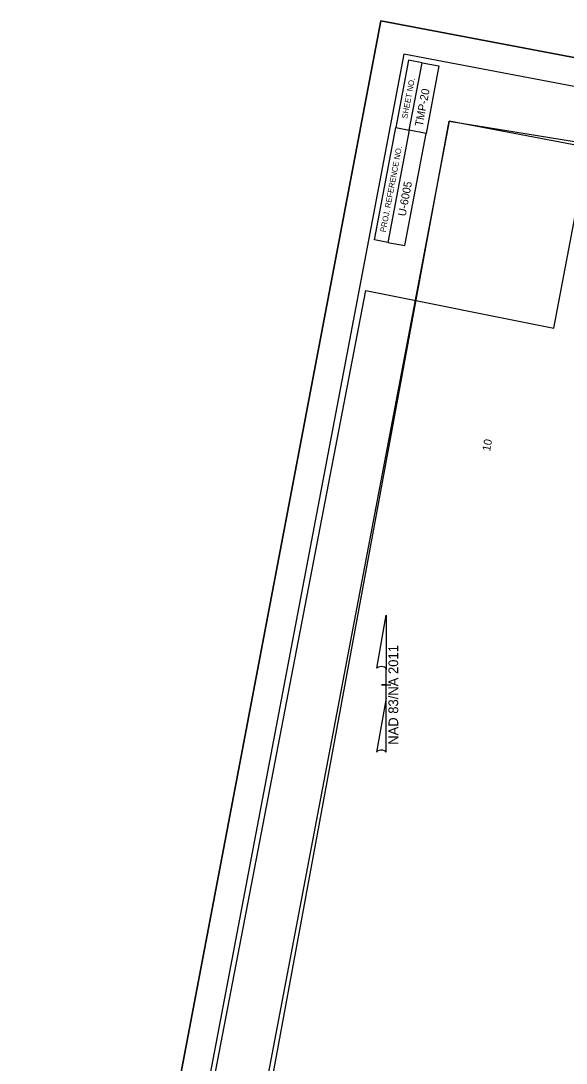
# Model space of a CAD drawing. Extents: x 1615680 to 1617075, y 898420 to 901168.
# Drawn here: x 1615680 to 1616157, y 900256 to 901168 of the extents above; entities that cross this region are included whole.
import ezdxf

# ---------------------------------------------------------------- set-up
doc = ezdxf.new("R2010")
doc.units = 0
for name, color, linetype in [('DEV BORDER CELL', 7, 'Continuous'), ('Prop Horizontal Alignment Tick Label', 7, 'Continuous'), ('Prop North Arrow NAD83 for Plan Sheets CELL', 7, 'Continuous'), ('Scratch_Level_0', 7, 'Continuous'), ('Sheet Clip Boundary CELL', 7, 'Continuous'), ('Sheet Plot Border Outside CELL', 7, 'Continuous')]:
    doc.layers.add(name, color=color, linetype=linetype)

msp = doc.modelspace()

# ---------------------------------------------------------------- linework, layer by layer
at = {"layer": 'DEV BORDER CELL'}
msp.add_line((1616019.39, 901072.79), (1616030.58, 901131.73), dxfattribs=at)
for points in [[(1616014.55, 901139.21), (1615734.74, 899665.53), (1616766.32, 899469.67), (1617046.12, 900943.35)], [(1616019.39, 901072.79), (1616030.58, 901131.73), (1616018.79, 901133.97), (1616007.6, 901075.03)], [(1616019.39, 901072.79), (1616030.58, 901131.73), (1616045.31, 901128.94), (1616034.12, 901069.99)], [(1615988.94, 900976.78), (1616007.6, 901075.03), (1616019.39, 901072.79), (1616000.73, 900974.54)], [(1616019.39, 901072.79), (1616000.73, 900974.54), (1616015.47, 900971.74), (1616034.12, 901069.99)]]:
    msp.add_lwpolyline(points, close=True, dxfattribs=at)
at = {"layer": 'Prop North Arrow NAD83 for Plan Sheets CELL'}
for p, q in [((1615990.96, 900601.99), (1615999.16, 900648.34)), ((1615999.21, 900648.34), (1615999.16, 900648.34)), ((1615999.21, 900648.34), (1615999.16, 900648.34)), ((1615999.21, 900648.34), (1615999.21, 900600.54)), ((1615999.21, 900575.74), (1615999.21, 900601.94)), ((1615999.21, 900600.54), (1615999.21, 900601.89)), ((1615995.21, 900587.34), (1615995.16, 900587.34)), ((1615998.76, 900587.34), (1615995.21, 900587.34)), ((1615995.26, 900587.34), (1616003.26, 900587.34)), ((1615999.21, 900575.74), (1615990.86, 900528.49)), ((1615999.26, 900528.69), (1615999.21, 900575.74))]:
    msp.add_line(p, q, dxfattribs=at)
for centre, start_param, end_param in [((1615995.1, 900601.49), 0.216388, 2.908219), ((1615995.1, 900528.32), 0.201328, 3.141593)]:
    msp.add_ellipse(centre, major_axis=(4.23, -0.03), ratio=0.461098, start_param=start_param, end_param=end_param, dxfattribs=at)
at = {"layer": 'Scratch_Level_0'}
msp.add_lwpolyline([(1616054.34, 901080.76), (1615793.19, 899705.33), (1616726.52, 899528.12), (1616890.46, 900391.55), (1616774.26, 900413.61), (1616871.48, 900925.61)], close=True, dxfattribs=at)
at = {"layer": 'Sheet Clip Boundary CELL'}
for points in [[(1616176.29, 901060.7), (1616848.46, 900914.27), (1616896.28, 900812.91), (1616872.94, 900688.21), (1616835.87, 900695.21), (1616753.94, 900262.18), (1616898.09, 900233.43), (1616734.79, 899562.1), (1616202.98, 899609.43), (1616198.71, 899647.14), (1615822.69, 899825.07), (1616054.34, 901080.76)], [(1616176.29, 901060.7), (1616914, 900899.99), (1616896.28, 900812.91), (1616872.94, 900688.21), (1616835.87, 900695.21), (1616753.94, 900262.18), (1616898.09, 900233.43), (1616747.89, 899480.25), (1615915.8, 899646.19), (1615751.76, 899738.03), (1615981.58, 900932.46), (1616145.94, 900899.57)]]:
    msp.add_lwpolyline(points, close=True, dxfattribs=at)
at = {"layer": 'Sheet Plot Border Outside CELL'}
for points in [[(1616760.47, 899304.87), (1615679.78, 899510.06), (1615994.65, 901168.43), (1617075.34, 900963.24)], [(1616760.47, 899304.87), (1617075.34, 900963.24), (1615994.65, 901168.43), (1615679.78, 899510.06)]]:
    msp.add_lwpolyline(points, close=True, dxfattribs=at)

# ---------------------------------------------------------------- texts
at = {"layer": 'DEV BORDER CELL'}
for s, height, rotation, p in [('SHEET NO.', 4.999, 79.24992, (1616017.69, 901082.61)), ('TMP-20', 7, 79.24937, (1616031.12, 901075.64)), ('PROJ. REFERENCE NO.', 4.9992, 79.24992, (1615998.81, 900983.16)), ('U-6005', 7, 79.24937, (1616016.2, 900997.05))]:
    msp.add_text(s, height=height, rotation=rotation, dxfattribs=at).set_placement(p)
at = {"layer": 'Prop Horizontal Alignment Tick Label'}
msp.add_text('10', height=7, rotation=79.16004, dxfattribs=at).set_placement((1616090.03, 900791.5))
at = {"layer": 'Prop North Arrow NAD83 for Plan Sheets CELL'}
msp.add_text('NAD 83/NA 2011', height=8.5, rotation=90, dxfattribs=at).set_placement((1616009.73, 900535.03))

doc.saveas('drawing.dxf')
